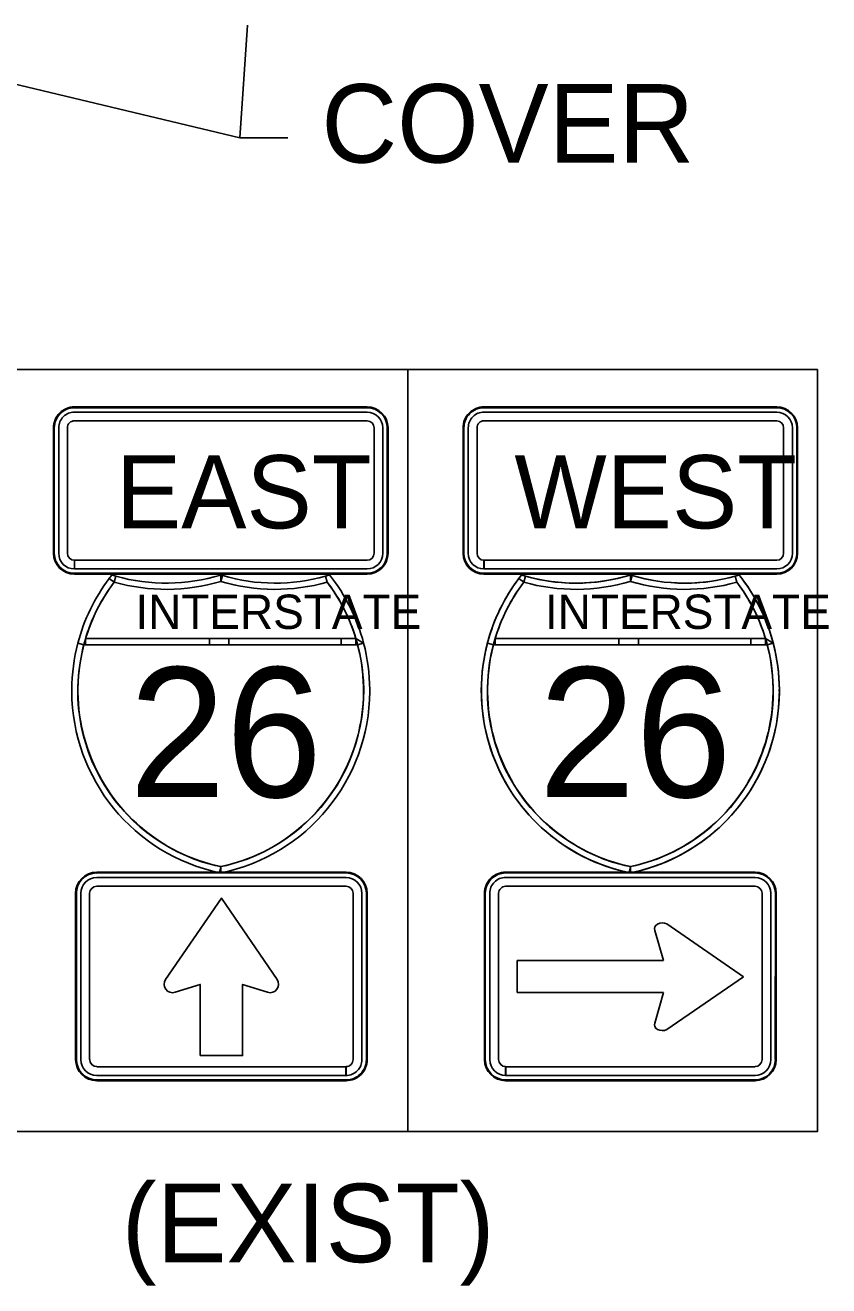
# Model space of a CAD drawing. Extents: x 886234 to 968767, y 455416 to 684046.
# Drawn here: x 920194 to 921347, y 514903 to 516711 of the extents above; entities that cross this region are included whole.
import ezdxf

# ---------------------------------------------------------------- set-up
doc = ezdxf.new("R2010")
doc.units = 0
for name, color, linetype in [('TC CONSTRUCTION PROPOSED ROADWAY SHADE', 7, 'Continuous'), ('TC DEV SIGN BLACK 239', 7, 'Continuous'), ('TC DEV SIGN BLACK ZERO', 7, 'Continuous'), ('TC DEV SIGN WHITE', 7, 'Continuous'), ('TC LABEL TEXT', 7, 'Continuous')]:
    doc.layers.add(name, color=color, linetype=linetype)

msp = doc.modelspace()

# ---------------------------------------------------------------- linework, layer by layer
at = {"layer": 'TC CONSTRUCTION PROPOSED ROADWAY SHADE'}
msp.add_lwpolyline([(920154.8, 516216.9), (920742.5, 516216.9), (920742.5, 515123.8), (920154.8, 515123.8)], close=True, dxfattribs=at)
at = {"layer": 'TC DEV SIGN BLACK 239'}
for p, q in [((920684.1, 516156), (920264.1, 516156)), ((920684.1, 516143.5), (920264.1, 516143.5)), ((921271.8, 516156), (920851.8, 516156)), ((921271.8, 516143.5), (920851.8, 516143.5)), ((920241.6, 516133.5), (920241.6, 515953.5)), ((920254.1, 516133.5), (920254.1, 515953.5)), ((920694.1, 515953.5), (920694.1, 516133.5)), ((920706.6, 515953.5), (920706.6, 516133.5)), ((920829.3, 516133.5), (920829.3, 515953.5)), ((920841.8, 516133.5), (920841.8, 515953.5)), ((921281.8, 515953.5), (921281.8, 516133.5)), ((921294.3, 515953.5), (921294.3, 516133.5)), ((920264.1, 515931), (920264.1, 515943.5)), ((920264.2, 515943.5), (920684.1, 515943.5)), ((920264.2, 515943.5), (920264.2, 515931)), ((920851.8, 515931), (920851.8, 515943.5)), ((920851.9, 515943.5), (921271.8, 515943.5)), ((920851.9, 515943.5), (920851.9, 515931)), ((920264.2, 515931), (920684.1, 515931)), ((920851.9, 515931), (921271.8, 515931)), ((920296.1, 515488.4), (920653.9, 515488.4)), ((920296.1, 515475.7), (920653.9, 515475.7)), ((921240.7, 515488.4), (920882.9, 515488.4)), ((921240.7, 515475.7), (920882.9, 515475.7)), ((920273.3, 515227.1), (920273.3, 515465.6)), ((920286, 515227.1), (920286, 515465.6)), ((920664.1, 515465.6), (920664.1, 515227.1)), ((920676.7, 515465.6), (920676.7, 515227.1)), ((920860.1, 515465.6), (920860.1, 515227.1)), ((920872.8, 515465.6), (920872.8, 515227.1)), ((921250.8, 515227.1), (921250.8, 515465.6)), ((921263.5, 515227.1), (921263.5, 515465.6)), ((921114, 515421.6), (921224, 515345.8)), ((921109.3, 515369.2), (921096.8, 515412.4)), ((920899.3, 515323.3), (920899.3, 515369.2)), ((920899.3, 515369.2), (921109.3, 515369.2)), ((921224, 515345.8), (921114, 515270.1)), ((921109.2, 515323.3), (920899.3, 515323.3)), ((921096.8, 515279.3), (921109.2, 515323.3)), ((920653.8, 515216.9), (920296.2, 515216.9)), ((920653.8, 515204.2), (920296.2, 515204.2)), ((920653.8, 515216.9), (920653.8, 515204.2)), ((920653.9, 515204.2), (920653.9, 515216.9)), ((920882.9, 515204.2), (920882.9, 515216.9)), ((920883, 515216.9), (921240.7, 515216.9)), ((920883, 515216.9), (920883, 515204.2)), ((920883, 515204.2), (921240.7, 515204.2))]:
    msp.add_line(p, q, dxfattribs=at)
for points in [[(920395, 515342.1), (920475.1, 515458.7), (920555.1, 515342.1)], [(920395, 515342.1), (920475.1, 515458.7), (920555.1, 515342.1)], [(920395, 515342.1), (920475.1, 515458.7), (920555.1, 515342.1)], [(920444.6, 515232.7), (920444.6, 515334.9), (920408.7, 515323.6)], [(920444.6, 515232.7), (920444.6, 515334.9), (920408.7, 515323.6)], [(920444.6, 515232.7), (920444.6, 515334.9), (920408.7, 515323.6)], [(920541.3, 515323.6), (920505.5, 515334.9), (920505.5, 515232.7), (920444.6, 515232.7)], [(920541.3, 515323.6), (920505.5, 515334.9), (920505.5, 515232.7), (920444.6, 515232.7)], [(920541.3, 515323.6), (920505.5, 515334.9), (920505.5, 515232.7), (920444.6, 515232.7)]]:
    msp.add_lwpolyline(points, dxfattribs=at)
for centre, start, end in [((920405, 515335.2), 145.5508, 287.601), ((920405, 515335.2), 145.5508, 287.601), ((920405, 515335.2), 145.5508, 287.601), ((920545, 515335.2), 252.399, 34.4492), ((920545, 515335.2), 252.399, 34.4492), ((920545, 515335.2), 252.399, 34.4492)]:
    msp.add_arc(centre, 12.2, start, end, dxfattribs=at)
for centre, major_axis, ratio, start_param, end_param in [((920264.1, 516133.5), (22.5, 0), 0.999865, 1.570796, 3.141593), ((920264.1, 516133.5), (10, 0), 0.999865, 1.570796, 3.141593), ((920684.1, 516133.5), (22.5, 0), 0.999865, 0, 1.570796), ((920684.1, 516133.5), (10, 0), 0.999865, 0, 1.570796), ((920851.8, 516133.5), (22.5, 0), 0.999865, 1.570796, 3.141593), ((920851.8, 516133.5), (10, 0), 0.999865, 1.570796, 3.141593), ((921271.8, 516133.5), (22.5, 0), 0.999865, 0, 1.570796), ((921271.8, 516133.5), (10, 0), 0.999865, 0, 1.570796), ((920264.1, 515953.5), (22.5, 0), 0.999865, 3.141593, 4.712389), ((920264.1, 515953.5), (10, 0), 0.999865, 3.141593, 4.712389), ((920684.1, 515953.5), (22.5, 0), 0.999865, 4.712389, 6.283185), ((920684.1, 515953.5), (10, 0), 0.999865, 4.712389, 6.283185), ((920851.8, 515953.5), (22.5, 0), 0.999865, 3.141593, 4.712389), ((920851.8, 515953.5), (10, 0), 0.999865, 3.141593, 4.712389), ((921271.8, 515953.5), (22.5, 0), 0.999865, 4.712389, 6.283185), ((921271.8, 515953.5), (10, 0), 0.999865, 4.712389, 6.283185), ((920296.1, 515465.6), (-22.8, 0), 0.999865, 4.712389, 6.283185), ((920296.1, 515465.6), (-10.1, 0), 0.999865, 4.712389, 6.283185), ((920653.9, 515465.6), (-22.8, 0), 0.999865, 3.141593, 4.712389), ((920653.9, 515465.6), (-10.1, 0), 0.999865, 3.141593, 4.712389), ((920882.9, 515465.6), (22.8, 0), 0.999865, 1.570796, 3.141593), ((920882.9, 515465.6), (10.1, 0), 0.999865, 1.570796, 3.141593), ((921240.7, 515465.6), (22.8, 0), 0.999865, 0, 1.570796), ((921240.7, 515465.6), (10.1, 0), 0.999865, 0, 1.570796), ((921107.6, 515414.9), (11.3, 0), 0.720018, 0.96961, 3.452569), ((921107.6, 515276.8), (11.3, 0), 0.720018, 2.830617, 5.313577), ((920296.2, 515227.1), (-22.8, 0), 0.999865, 0, 1.570796), ((920296.2, 515227.1), (-10.1, 0), 0.999865, 0, 1.570796), ((920653.9, 515227.1), (-22.8, 0), 0.999865, 1.570796, 3.141593), ((920653.9, 515227.1), (-10.1, 0), 0.999865, 1.570796, 3.141593), ((920882.9, 515227.1), (22.8, 0), 0.999865, 3.141593, 4.712389), ((920882.9, 515227.1), (10.1, 0), 0.999865, 3.141593, 4.712389), ((921240.7, 515227.1), (22.8, 0), 0.999865, 4.712389, 6.283185), ((921240.7, 515227.1), (10.1, 0), 0.999865, 4.712389, 6.283185)]:
    msp.add_ellipse(centre, major_axis=major_axis, ratio=ratio, start_param=start_param, end_param=end_param, dxfattribs=at)
at = {"layer": 'TC DEV SIGN BLACK ZERO'}
for p, q in [((920684.1, 516163.5), (920264.1, 516163.5)), ((920264.1, 516162.3), (920264.1, 516162.3)), ((920684.1, 516162.3), (920264.1, 516162.3)), ((920684.1, 516162.3), (920684.1, 516162.3)), ((921271.8, 516163.5), (920851.8, 516163.5)), ((920851.8, 516162.3), (920851.8, 516162.3)), ((921271.8, 516162.3), (920851.8, 516162.3)), ((921271.8, 516162.3), (921271.8, 516162.3)), ((920234.1, 516133.5), (920234.1, 515953.5)), ((920235.3, 516133.5), (920235.3, 515953.5)), ((920235.3, 516133.5), (920235.3, 516133.5)), ((920712.9, 516133.5), (920712.9, 516133.5)), ((920712.9, 515953.5), (920712.9, 516133.5)), ((920714.1, 515953.5), (920714.1, 516133.5)), ((920821.8, 516133.5), (920821.8, 515953.5)), ((920823, 516133.5), (920823, 515953.5)), ((920823, 516133.5), (920823, 516133.5)), ((921300.6, 516133.5), (921300.6, 516133.5)), ((921300.6, 515953.5), (921300.6, 516133.5)), ((921301.8, 515953.5), (921301.8, 516133.5)), ((920235.3, 515953.5), (920235.3, 515953.5)), ((920712.9, 515953.5), (920712.9, 515953.5)), ((920823, 515953.5), (920823, 515953.5)), ((921300.6, 515953.5), (921300.6, 515953.5)), ((920264.1, 515923.5), (920264.1, 515924.8)), ((920264.1, 515924.8), (920264.1, 515924.8)), ((920264.1, 515924.8), (920684.1, 515924.8)), ((920264.1, 515924.8), (920264.1, 515923.5)), ((920264.1, 515923.5), (920684.1, 515923.5)), ((920321.3, 515912), (920323.7, 515920.6)), ((920474.3, 515913), (920474.1, 515922.3)), ((920474.3, 515913.6), (920474.1, 515922.3)), ((920624.5, 515920.6), (920626.9, 515912)), ((920684.1, 515924.8), (920684.1, 515924.8)), ((920851.8, 515923.5), (920851.8, 515924.8)), ((920851.8, 515924.8), (920851.8, 515924.8)), ((920851.8, 515924.8), (921271.8, 515924.8)), ((920851.8, 515924.8), (920851.8, 515923.5)), ((920851.8, 515923.5), (921271.8, 515923.5)), ((920909, 515912), (920911.4, 515920.6)), ((921062, 515913), (921061.8, 515922.3)), ((921062, 515913.6), (921061.8, 515922.3)), ((921212.2, 515920.6), (921214.6, 515912)), ((921271.8, 515924.8), (921271.8, 515924.8)), ((920277.7, 515822.2), (920670.5, 515822.2)), ((920277.7, 515822.2), (920280.2, 515822.2)), ((920280.2, 515831.1), (920667.9, 515831.1)), ((920457.8, 515831.1), (920280.2, 515831.1)), ((920280.2, 515822.2), (920457.8, 515822.2)), ((920485.9, 515831.1), (920457.8, 515831.1)), ((920457.8, 515822.2), (920485.9, 515822.2)), ((920647, 515831.1), (920485.9, 515831.1)), ((920485.9, 515822.2), (920647, 515822.2)), ((920667.9, 515831.1), (920647, 515831.1)), ((920647, 515822.2), (920667.9, 515822.2)), ((920679.1, 515824.5), (920667.9, 515831.1)), ((920670.3, 515822.8), (920667.9, 515822.2)), ((920667.9, 515822.2), (920670.5, 515822.2)), ((920865.4, 515822.2), (921258.2, 515822.2)), ((920865.4, 515822.2), (920867.9, 515822.2)), ((920867.9, 515831.1), (921255.7, 515831.1)), ((921045.5, 515831.1), (920867.9, 515831.1)), ((920867.9, 515822.2), (921045.5, 515822.2)), ((921073.6, 515831.1), (921045.5, 515831.1)), ((921045.5, 515822.2), (921073.6, 515822.2)), ((921234.7, 515831.1), (921073.6, 515831.1)), ((921073.6, 515822.2), (921234.7, 515822.2)), ((921255.7, 515831.1), (921234.7, 515831.1)), ((921234.7, 515822.2), (921255.7, 515822.2)), ((921266.8, 515824.5), (921255.7, 515831.1)), ((921258, 515822.8), (921255.7, 515822.2)), ((921255.7, 515822.2), (921258.2, 515822.2)), ((920260.3, 515757.9), (920260.3, 515755.2)), ((920687.8, 515755.2), (920687.8, 515758)), ((920848, 515757.9), (920848, 515755.2)), ((921275.5, 515755.2), (921275.5, 515758)), ((920296.1, 515496), (920653.9, 515496)), ((920296.1, 515494.7), (920653.9, 515494.8)), ((920296.1, 515494.7), (920296.1, 515494.8)), ((920474.1, 515494.8), (920474.1, 515503.9)), ((920653.9, 515494.8), (920653.9, 515494.8)), ((921240.7, 515496), (920882.9, 515496)), ((920882.9, 515494.8), (920882.9, 515494.8)), ((921240.7, 515494.7), (920882.9, 515494.8)), ((921240.7, 515494.7), (921240.7, 515494.8)), ((920265.7, 515227.1), (920265.7, 515465.6)), ((920267, 515465.6), (920267, 515465.6)), ((920267, 515227.1), (920267, 515465.6)), ((920683.1, 515465.6), (920683.1, 515227.1)), ((920683.1, 515465.6), (920683.1, 515465.6)), ((920684.3, 515465.6), (920684.4, 515227.1)), ((920852.5, 515465.6), (920852.5, 515227.1)), ((920853.7, 515465.6), (920853.7, 515227.1)), ((920853.7, 515465.6), (920853.7, 515465.6)), ((921269.8, 515465.6), (921269.9, 515465.6)), ((921269.8, 515227.1), (921269.9, 515465.6)), ((921271.1, 515227.1), (921271.1, 515465.6)), ((920267, 515227.1), (920267, 515227.1)), ((920683.1, 515227.1), (920683.1, 515227.1)), ((920853.7, 515227.1), (920853.7, 515227.1)), ((921269.8, 515227.1), (921269.8, 515227.1)), ((920296.2, 515197.9), (920296.2, 515197.9)), ((920653.9, 515197.9), (920296.2, 515197.9)), ((920653.9, 515196.6), (920296.2, 515196.6)), ((920653.9, 515196.6), (920653.9, 515197.9)), ((920653.9, 515197.9), (920653.9, 515197.9)), ((920653.9, 515197.9), (920653.9, 515196.6)), ((920882.9, 515196.6), (920882.9, 515197.9)), ((920882.9, 515197.9), (920882.9, 515197.9)), ((920882.9, 515197.9), (921240.7, 515197.9)), ((920882.9, 515197.9), (920882.9, 515196.6)), ((920882.9, 515196.6), (921240.7, 515196.6)), ((921240.7, 515197.9), (921240.7, 515197.9))]:
    msp.add_line(p, q, dxfattribs=at)
for points in [[(920314.2, 515917.4), (920321.3, 515912)], [(920321.3, 515912), (920314.2, 515917.4)], [(920317.9, 515922.3), (920317.9, 515922.3), (920317.9, 515922.3)], [(920323.7, 515920.6), (920321.3, 515912)], [(920474.1, 515913), (920474.3, 515913.6)], [(920474.3, 515922.2), (920474.3, 515913.6), (920476.8, 515921.4)], [(920476.8, 515921.4), (920474.3, 515913)], [(920626.9, 515912), (920624.5, 515920.6)], [(920630.3, 515922.3), (920630.3, 515922.3), (920630.2, 515922.3)], [(920901.9, 515917.4), (920909, 515912)], [(920909, 515912), (920901.9, 515917.4)], [(920905.7, 515922.3), (920905.6, 515922.3), (920905.6, 515922.3)], [(920911.4, 515920.6), (920909, 515912)], [(921061.8, 515913), (921062, 515913.6)], [(921062, 515922.2), (921062, 515913.6), (921064.5, 515921.4)], [(921064.5, 515921.4), (921062, 515913)], [(921214.6, 515912), (921212.2, 515920.6)], [(921218, 515922.3), (921218, 515922.3), (921217.9, 515922.3)], [(920269.1, 515824.5), (920277.7, 515822.2)], [(920277.7, 515822.2), (920269.1, 515824.5)], [(920280.2, 515831.1), (920280.2, 515822.2)], [(920280.2, 515822.2), (920280.2, 515831.1)], [(920457.8, 515822.2), (920457.8, 515831.1)], [(920457.8, 515831.1), (920457.8, 515822.2)], [(920485.9, 515831.1), (920485.9, 515822.2)], [(920485.9, 515822.2), (920485.9, 515831.1)], [(920647, 515822.2), (920647, 515831.1)], [(920647, 515831.1), (920647, 515822.2)], [(920667.9, 515831.1), (920679.1, 515824.5)], [(920667.9, 515822.2), (920667.9, 515831.1)], [(920667.9, 515831.1), (920667.9, 515822.2), (920670.3, 515822.8), (920667.9, 515831.1)], [(920670.5, 515822.2), (920670.3, 515822.8)], [(920679.1, 515824.5), (920670.5, 515822.2)], [(920670.5, 515822.2), (920679.1, 515824.5)], [(920856.8, 515824.5), (920865.4, 515822.2)], [(920865.4, 515822.2), (920856.8, 515824.5)], [(920867.9, 515831.1), (920867.9, 515822.2)], [(920867.9, 515822.2), (920867.9, 515831.1)], [(921045.5, 515822.2), (921045.5, 515831.1)], [(921045.5, 515831.1), (921045.5, 515822.2)], [(921073.6, 515831.1), (921073.6, 515822.2)], [(921073.6, 515822.2), (921073.6, 515831.1)], [(921234.7, 515822.2), (921234.7, 515831.1)], [(921234.7, 515831.1), (921234.7, 515822.2)], [(921255.7, 515831.1), (921266.8, 515824.5)], [(921255.7, 515822.2), (921255.7, 515831.1)], [(921255.7, 515831.1), (921255.7, 515822.2), (921258, 515822.8), (921255.7, 515831.1)], [(921258.2, 515822.2), (921258, 515822.8)], [(921266.8, 515824.5), (921258.2, 515822.2)], [(921258.2, 515822.2), (921266.8, 515824.5)], [(920472.2, 515495.1), (920474.1, 515503.9)], [(920474.1, 515503.9), (920472.2, 515495.1), (920474.1, 515494.8)], [(920474.1, 515503.9), (920474.1, 515494.8)], [(921060, 515495.1), (921061.8, 515503.9)], [(921061.8, 515503.9), (921061.8, 515494.8)]]:
    msp.add_lwpolyline(points, dxfattribs=at)
for centre, radius, start, end in [((920527.5, 515756.6), 267.2, 142.9968, 165.2769), ((920527.5, 515756.6), 258.3, 142.9968, 258.0595), ((920527.5, 515756.6), 258.3, 142.9968, 165.2769), ((920527.5, 515756.6), 267.2, 141.6709, 142.9968), ((920396, 516177.8), 267.2, 253.0099, 254.2907), ((920396, 516177.8), 276.1, 254.2907, 286.4259), ((920396, 516177.8), 276.1, 254.2907, 286.4259), ((920396, 516177.8), 267.2, 254.2907, 286.9893), ((920552.2, 516177.8), 276.1, 253.5741, 285.7093), ((920420.7, 515756.6), 258.3, 281.9405, 37.0032), ((920552.2, 516177.8), 267.2, 253.0588, 253.6206), ((920552.3, 516177.4), 275.7, 253.5731, 285.7093), ((920552.2, 516177.8), 267.2, 253.6206, 285.7093), ((920552.2, 516177.8), 267.2, 285.7093, 286.9901), ((920420.7, 515756.6), 258.3, 16.7759, 37.0032), ((920420.7, 515756.6), 267.2, 14.7231, 38.3291), ((921115.2, 515756.6), 267.2, 141.6693, 258.4631), ((921115.2, 515756.6), 267.2, 142.9968, 165.2769), ((921115.2, 515756.6), 258.3, 142.9968, 258.0595), ((921115.2, 515756.6), 258.3, 142.9968, 165.2769), ((921115.2, 515756.6), 267.2, 141.6709, 142.9968), ((920983.7, 516177.8), 267.2, 253.0062, 286.9901), ((920983.7, 516177.8), 267.2, 253.0099, 254.2907), ((920983.7, 516177.8), 276.1, 254.2907, 286.4259), ((920983.7, 516177.8), 276.1, 254.2907, 286.4259), ((920983.7, 516177.8), 267.2, 254.2907, 286.9893), ((921139.9, 516177.8), 267.2, 253.0099, 286.9938), ((921008.4, 515756.6), 267.2, 281.5369, 38.3307), ((921139.9, 516177.8), 276.1, 253.5741, 285.7093), ((921008.4, 515756.6), 258.3, 281.9405, 37.0032), ((921139.9, 516177.8), 267.2, 253.0588, 253.6206), ((921140, 516177.4), 275.7, 253.5731, 285.7093), ((921139.9, 516177.8), 267.2, 253.6206, 285.7093), ((921139.9, 516177.8), 267.2, 285.7093, 286.9901), ((921008.4, 515756.6), 258.3, 16.7759, 37.0032), ((921008.4, 515756.6), 267.2, 14.7231, 38.3291), ((920527.5, 515756.6), 267.2, 165.2769, 179.7177), ((920526.3, 515755.8), 257.3, 165.0438, 258.3001), ((920527.5, 515756.6), 258.3, 163.2241, 165.2769), ((920421.9, 515755.8), 257.3, 281.7196, 14.964), ((920420.7, 515756.6), 258.3, 14.7231, 16.7759), ((920420.7, 515756.6), 267.2, 0.2997, 14.7231), ((921115.2, 515756.6), 267.2, 165.2769, 179.7177), ((921114, 515755.8), 257.3, 165.0438, 258.3001), ((921115.2, 515756.6), 258.3, 163.2241, 165.2769), ((921009.6, 515755.8), 257.3, 281.7196, 14.964), ((921008.4, 515756.6), 258.3, 14.7231, 16.7759), ((921008.4, 515756.6), 267.2, 0.2997, 14.7231), ((920527.5, 515756.6), 267.2, 180.2823, 258.0591), ((920420.7, 515756.6), 267.2, 281.537, 359.7003), ((921115.2, 515756.6), 267.2, 180.2823, 258.0591), ((921008.4, 515756.6), 267.2, 281.537, 359.7003), ((920420.7, 515756.6), 258.3, 281.9405, 281.9604), ((920527.5, 515756.6), 267.2, 258.458, 258.463), ((920420.7, 515756.6), 267.2, 281.5369590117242, 281.53700435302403), ((921008.4, 515756.6), 258.3, 281.9405, 281.9604)]:
    msp.add_arc(centre, radius, start, end, dxfattribs=at)
for centre, major_axis, start_param, end_param in [((920264.1, 516133.5), (30, 0), 1.570796, 3.141593), ((920264.1, 516133.5), (28.8, 0), 1.570796, 3.141593), ((920684.1, 516133.5), (30, 0), 0, 1.570796), ((920684.1, 516133.5), (28.8, 0), 0, 1.570796), ((920851.8, 516133.5), (30, 0), 1.570796, 3.141593), ((920851.8, 516133.5), (28.8, 0), 1.570796, 3.141593), ((921271.8, 516133.5), (30, 0), 0, 1.570796), ((921271.8, 516133.5), (28.8, 0), 0, 1.570796), ((920264.1, 515953.5), (30, 0), 3.141593, 4.712389), ((920264.1, 515953.5), (28.8, 0), 3.141593, 4.712389), ((920684.1, 515953.5), (30, 0), 4.712389, 6.283185), ((920684.1, 515953.5), (28.8, 0), 4.712389, 6.283185), ((920851.8, 515953.5), (30, 0), 3.141593, 4.712389), ((920851.8, 515953.5), (28.8, 0), 3.141593, 4.712389), ((921271.8, 515953.5), (30, 0), 4.712389, 6.283185), ((921271.8, 515953.5), (28.8, 0), 4.712389, 6.283185), ((920296.1, 515465.6), (-30.4, 0), 4.712389, 6.283185), ((920296.1, 515465.6), (-29.2, 0), 4.712389, 6.283185), ((920653.9, 515465.6), (-30.4, 0), 3.141593, 4.712389), ((920653.9, 515465.6), (-29.2, 0), 3.141593, 4.712389), ((920882.9, 515465.6), (30.4, 0), 1.570796, 3.141593), ((920882.9, 515465.6), (29.2, 0), 1.570796, 3.141593), ((921240.7, 515465.6), (30.4, 0), 0, 1.570796), ((921240.7, 515465.6), (29.2, 0), 0, 1.570796), ((920296.2, 515227.1), (-30.4, 0), 0, 1.570796), ((920296.2, 515227.1), (-29.2, 0), 0, 1.570796), ((920653.9, 515227.1), (-30.4, 0), 1.570796, 3.141593), ((920653.9, 515227.1), (-29.2, 0), 1.570796, 3.141593), ((920882.9, 515227.1), (30.4, 0), 3.141593, 4.712389), ((920882.9, 515227.1), (29.2, 0), 3.141593, 4.712389), ((921240.7, 515227.1), (30.4, 0), 4.712389, 6.283185), ((921240.7, 515227.1), (29.2, 0), 4.712389, 6.283185)]:
    msp.add_ellipse(centre, major_axis=major_axis, ratio=0.999865, start_param=start_param, end_param=end_param, dxfattribs=at)
at = {"layer": 'TC DEV SIGN WHITE'}
for p, q in [((920684.1, 516163.5), (920264.1, 516163.5)), ((921271.8, 516163.5), (920851.8, 516163.5)), ((920234.1, 516133.5), (920234.1, 515953.5)), ((920714.1, 515953.5), (920714.1, 516133.5)), ((920821.8, 516133.5), (920821.8, 515953.5)), ((921301.8, 515953.5), (921301.8, 516133.5)), ((920264.1, 515923.5), (920684.1, 515923.5)), ((920851.8, 515923.5), (921271.8, 515923.5)), ((920296.1, 515496), (920653.9, 515496)), ((921240.7, 515496), (920882.9, 515496)), ((921061.8, 515494.8), (921061.8, 515503.9)), ((920265.7, 515227.1), (920265.7, 515465.6)), ((920684.3, 515465.6), (920684.4, 515227.1)), ((920852.5, 515465.6), (920852.5, 515227.1)), ((921271.1, 515227.1), (921271.1, 515465.6)), ((920653.9, 515196.6), (920296.2, 515196.6)), ((920882.9, 515196.6), (921240.7, 515196.6))]:
    msp.add_line(p, q, dxfattribs=at)
msp.add_lwpolyline([(921061.8, 515503.9), (921060, 515495.1), (921061.8, 515494.8)], dxfattribs=at)
for centre, start, end in [((921115.2, 515756.6), 258.458, 258.463), ((921008.4, 515756.6), 281.5369590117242, 281.53700435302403)]:
    msp.add_arc(centre, 267.2, start, end, dxfattribs=at)
for centre, major_axis, start_param, end_param in [((920264.1, 516133.5), (30, 0), 1.570796, 3.141593), ((920684.1, 516133.5), (30, 0), 0, 1.570796), ((920851.8, 516133.5), (30, 0), 1.570796, 3.141593), ((921271.8, 516133.5), (30, 0), 0, 1.570796), ((920264.1, 515953.5), (30, 0), 3.141593, 4.712389), ((920684.1, 515953.5), (30, 0), 4.712389, 6.283185), ((920851.8, 515953.5), (30, 0), 3.141593, 4.712389), ((921271.8, 515953.5), (30, 0), 4.712389, 6.283185), ((920296.1, 515465.6), (-30.4, 0), 4.712389, 6.283185), ((920653.9, 515465.6), (-30.4, 0), 3.141593, 4.712389), ((920882.9, 515465.6), (30.4, 0), 1.570796, 3.141593), ((921240.7, 515465.6), (30.4, 0), 0, 1.570796), ((920296.2, 515227.1), (-30.4, 0), 0, 1.570796), ((920653.9, 515227.1), (-30.4, 0), 1.570796, 3.141593), ((920882.9, 515227.1), (30.4, 0), 3.141593, 4.712389), ((921240.7, 515227.1), (30.4, 0), 4.712389, 6.283185)]:
    msp.add_ellipse(centre, major_axis=major_axis, ratio=0.999865, start_param=start_param, end_param=end_param, dxfattribs=at)
at = {"layer": 'TC LABEL TEXT'}
msp.add_line((920501.5, 516549.5), (919825.2, 516711.1), dxfattribs=at)
msp.add_lwpolyline([(920570.3, 516549.7), (920501.5, 516549.5), (920512.7, 516711.1)], dxfattribs=at)
for points in [[(920154.8, 516216.9), (920742.5, 516216.9), (920742.5, 515123.8), (920154.8, 515123.8)], [(920742.5, 516216.9), (921330.2, 516216.9), (921330.2, 515123.8), (920742.5, 515123.8)]]:
    msp.add_lwpolyline(points, close=True, dxfattribs=at)

# ---------------------------------------------------------------- texts
at = {"layer": 'TC DEV SIGN BLACK 239'}
for s, p in [('EAST', (920323.7, 515989.2)), ('WEST', (920895.4, 515989.2))]:
    msp.add_text(s, height=105, rotation=360, dxfattribs=at).set_placement(p)
at = {"layer": 'TC DEV SIGN BLACK ZERO'}
for s, height, p in [('INTERSTATE', 49.28, (920351.6, 515844.9)), ('INTERSTATE', 49.28, (920939.3, 515844.9)), ('26', 186.16, (920342.7, 515603.6)), ('26', 186.16, (920930.4, 515603.6))]:
    msp.add_text(s, height=height, rotation=360, dxfattribs=at).set_placement(p)
at = {"layer": 'TC LABEL TEXT'}
for s, p in [('COVER', (920618.5, 516514)), ('(EXIST)', (920332, 514936.4))]:
    msp.add_text(s, height=112.5, dxfattribs=at).set_placement(p)

doc.saveas('drawing.dxf')
